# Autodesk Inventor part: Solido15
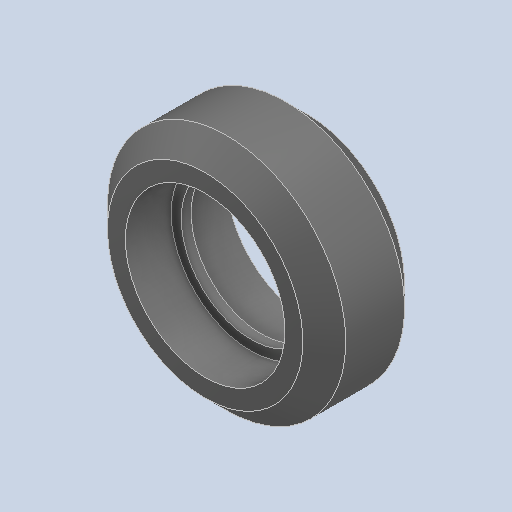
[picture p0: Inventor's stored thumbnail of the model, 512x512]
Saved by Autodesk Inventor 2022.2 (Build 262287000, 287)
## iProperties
Created: 2024-10
Part Number: Solido15
Material: Generico
Document SubType Name: Modeling
Designer: 18907419
Density: 1 g/cm^3
Appearance: Default
Author: 18907419
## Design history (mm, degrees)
feature "Solido15"
node "Solido1"
